(* Logix 5000 project; controller Electronic_Displays vendor 1 type 14 code 65 rev 17.4; software revision 17.01; part 3 of 9 *)
(* tags used below, declared in another part *)
   EDV : LEDSIGN;
   ENABLE : DINT;

ADD_ON_INSTRUCTION NumberSignRTA   (* revision 1.0, ExecuteEnableInFalse *)
// Number Sign
// Send only Numbers
// Revision note:
// Original Release
// 03-30-2013
// c.elston
VAR_IN_OUT
   Address : STRING; {required}   // "01" = address 01 "02" = address 02 etc...(see protocol)
   NumberValue : DINT; {required}   // Actual number value (DINT Format)
END_VAR
VAR_OUTPUT
   EN : BOOL; {visible}   // Instruction Interface Enable Bit
   DN : BOOL; {visible}   // Instruction Interface Done Bit
   ER : BOOL; {visible}   // Instruction Interface Error Bit
   IP : BOOL; {visible}   // Instruction Interface InProcess Bit
END_VAR
VAR_IN_OUT
   map_SignInput : SINT[100]; {required}   // Ethernet/IP LEDSIGN.I Data I/O Mapping
   map_SignOutput : SINT[100]; {required}   // Ethernet/IP LEDSIGN.O Data I/O Mapping
   PacketSent : STRING; {required}   // The actual packet sent to the sign.
END_VAR
VAR
   SEQ : DINT;   // Sequence Number
   OktoCycle : BOOL;   // Ok to Cycle
   InCycle : BOOL;   // Incycle
   Error : BOOL;   // Error
   Enabled : BOOL;   // Enable ON Bit
   Done : BOOL;   // Done
   Disabled : BOOL;   // Disabled OFF Bit
   SignETX : STRING := '$03';   // DO NOT EDIT = $03 the number sign protocol is different than EDV signs
   SignAddress : STRING;
   SignSTX : STRING := '$02';   // DO NOT EDIT = $02 the number sign protocol is different than EDV signs
   SignNULL : STRING;
   TotalPacketCount : DINT[7];   // Total Character Count
   Select : DINT;   // Packet Array Select
   PacketMax : DINT := 82;   // Max Packet Count
   PacketCount : DINT[7];
   Packet6Offset : DINT;
   Packet5Offset : DINT;
   Packet4Offset : DINT;
   Packet3Offset : DINT;
   Packet2Offset : DINT;
   Packet1Offset : DINT;
   Packet : STRING[7];   // Packet Array to send to sign
   SignNumberValue : DINT;
   SignVariable1Value : STRING;
   SignNumberValue1 : STRING;
   SignNumberValueSTRING : STRING;
END_VAR

ROUTINE EnableInFalse   (* ladder *)
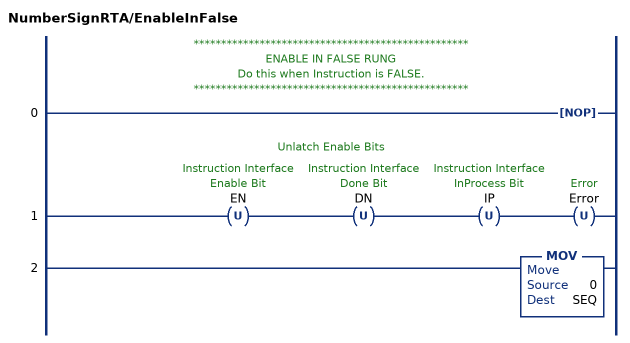
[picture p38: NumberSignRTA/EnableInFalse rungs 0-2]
   // **************************************************
   // ENABLE IN FALSE RUNG
   // Do this when Instruction is FALSE.
   // **************************************************
   0: NOP();
   // Unlatch Enable Bits
   1: OTU(EN)OTU(DN)OTU(IP)OTU(Error);
   2: MOV(0,SEQ);
END_ROUTINE

ROUTINE Logic   (* ladder *)
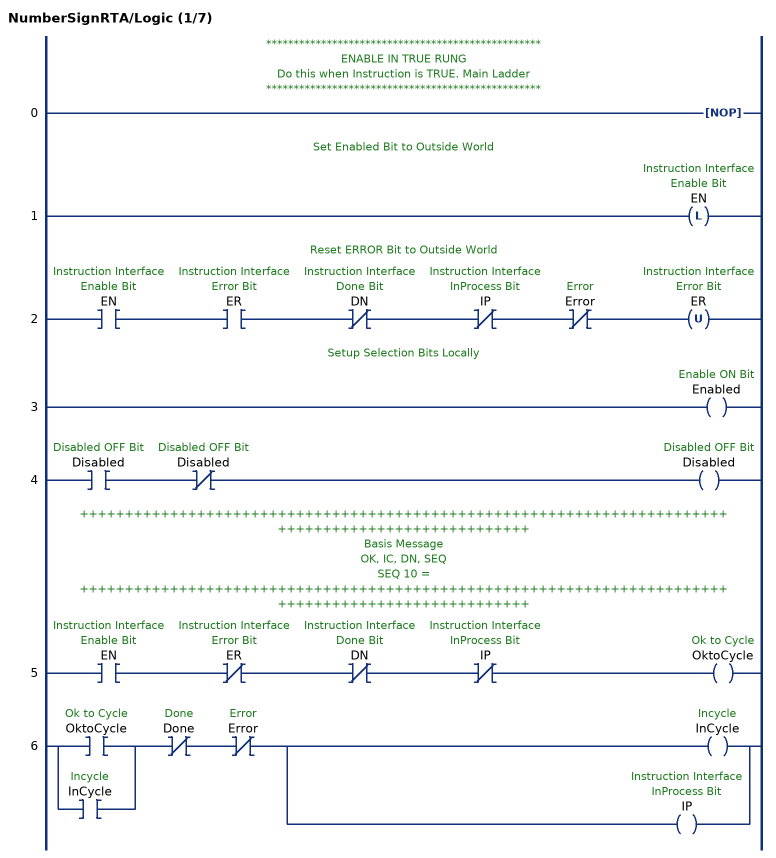
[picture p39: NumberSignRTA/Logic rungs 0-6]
   // **************************************************
   // ENABLE IN TRUE RUNG
   // Do this when Instruction is TRUE. Main Ladder
   // **************************************************
   0: NOP();
   // Set Enabled Bit to Outside World
   1: OTL(EN);
   // Reset ERROR Bit to Outside World
   2: XIC(EN)XIC(ER)XIO(DN)XIO(IP)XIO(Error)OTU(ER);
   // Setup Selection Bits Locally
   3: OTE(Enabled);
   4: XIC(Disabled)XIO(Disabled)OTE(Disabled);
   // ++++++++++++++++++++++++++++++++++++++++++++++++++++++++++++++++++++++++++++++++++++++++++++++++++++
   // Basis Message
   // OK, IC, DN, SEQ
   // SEQ 10 =
   // ++++++++++++++++++++++++++++++++++++++++++++++++++++++++++++++++++++++++++++++++++++++++++++++++++++
   5: XIC(EN)XIO(ER)XIO(DN)XIO(IP)OTE(OktoCycle);
   6: [XIC(OktoCycle) ,XIC(InCycle) ]XIO(Done)XIO(Error)[OTE(InCycle) ,OTE(IP) ];
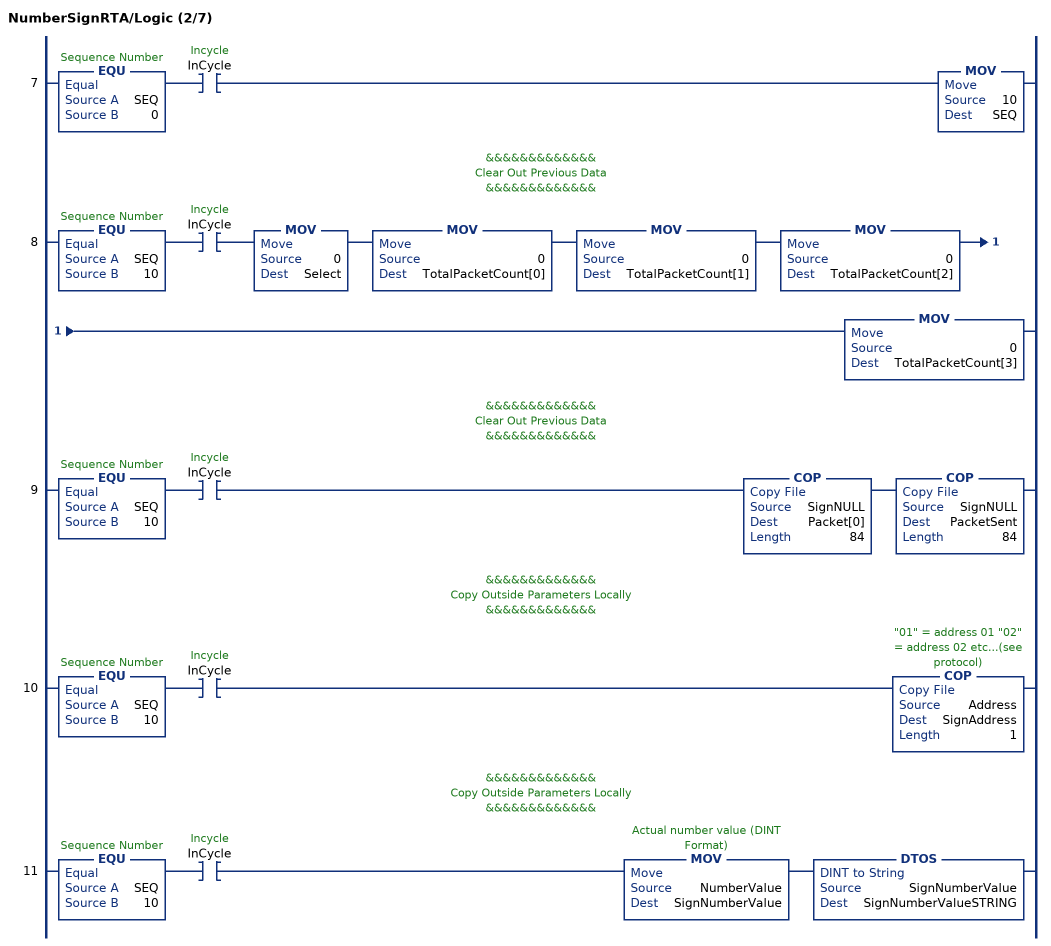
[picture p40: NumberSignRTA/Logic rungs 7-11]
   7: EQU(SEQ,0)XIC(InCycle)MOV(10,SEQ);
   // &&&&&&&&&&&&&
   // Clear Out Previous Data
   // &&&&&&&&&&&&&
   8: EQU(SEQ,10)XIC(InCycle)MOV(0,Select)MOV(0,TotalPacketCount[0])MOV(0,TotalPacketCount[1])MOV(0,TotalPacketCount[2])MOV(0,TotalPacketCount[3]);
   // &&&&&&&&&&&&&
   // Clear Out Previous Data
   // &&&&&&&&&&&&&
   9: EQU(SEQ,10)XIC(InCycle)COP(SignNULL,Packet[0],84)COP(SignNULL,PacketSent,84);
   // &&&&&&&&&&&&&
   // Copy Outside Parameters Locally
   // &&&&&&&&&&&&&
   10: EQU(SEQ,10)XIC(InCycle)COP(Address,SignAddress,1);
   // &&&&&&&&&&&&&
   // Copy Outside Parameters Locally
   // &&&&&&&&&&&&&
   11: EQU(SEQ,10)XIC(InCycle)MOV(NumberValue,SignNumberValue)DTOS(SignNumberValue,SignNumberValueSTRING);
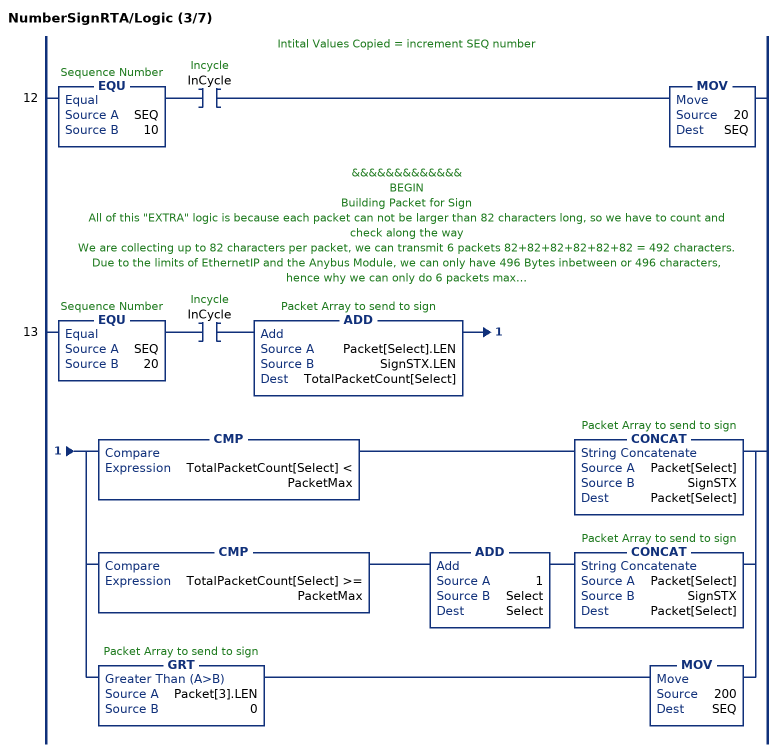
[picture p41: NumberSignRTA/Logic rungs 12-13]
   // Intital Values Copied = increment SEQ number
   12: EQU(SEQ,10)XIC(InCycle)MOV(20,SEQ);
   // &&&&&&&&&&&&&
   // BEGIN
   // Building Packet for Sign
   // All of this "EXTRA" logic is because each packet can not be larger than 82 characters long, so we have to count and check along the way
   // We are collecting up to 82 characters per packet, we can transmit 6 packets 82+82+82+82+82+82 = 492 characters.
   // Due to the limits of EthernetIP and the Anybus Module, we can only have 496 Bytes inbetween or 496 characters, hence why we can only do 6 packets max.
   // Once we exceed this, we will fault and ERROR trap any windy typing people.
   // In this instruction below, it's so small, we are only using 3 packets max.
   // &&&&&&&&&&&&&
   13: EQU(SEQ,20)XIC(InCycle)ADD(Packet[Select].LEN,SignSTX.LEN,TotalPacketCount[Select])[CMP(TotalPacketCount[Select] < PacketMax) CONCAT(Packet[Select],SignSTX,Packet[Select]) ,CMP(TotalPacketCount[Select] >= PacketMax) ADD(1,Select,Select) CONCAT(Packet[Select],SignSTX,Packet[Select]) ,GRT(Packet[3].LEN,0) MOV(200,SEQ) ];
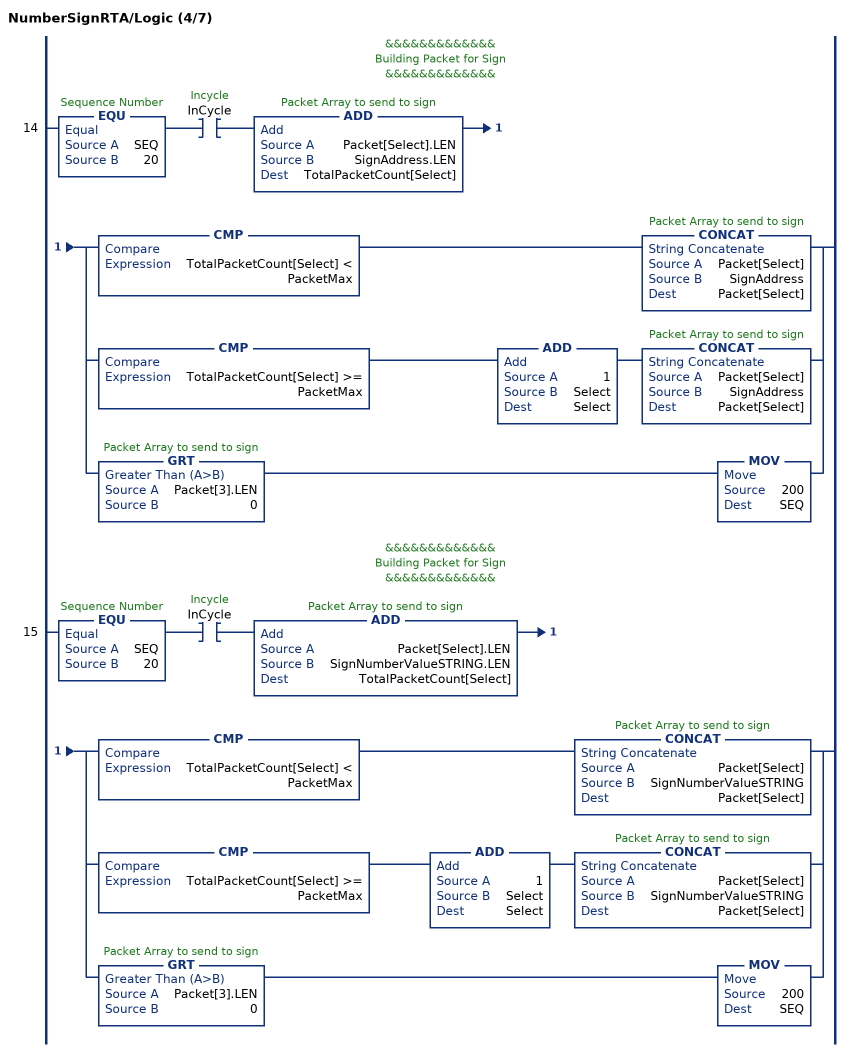
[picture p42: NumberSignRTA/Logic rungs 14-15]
   // &&&&&&&&&&&&&
   // Building Packet for Sign
   // &&&&&&&&&&&&&
   14: EQU(SEQ,20)XIC(InCycle)ADD(Packet[Select].LEN,SignAddress.LEN,TotalPacketCount[Select])[CMP(TotalPacketCount[Select] < PacketMax) CONCAT(Packet[Select],SignAddress,Packet[Select]) ,CMP(TotalPacketCount[Select] >= PacketMax) ADD(1,Select,Select) CONCAT(Packet[Select],SignAddress,Packet[Select]) ,GRT(Packet[3].LEN,0) MOV(200,SEQ) ];
   // &&&&&&&&&&&&&
   // Building Packet for Sign
   // &&&&&&&&&&&&&
   15: EQU(SEQ,20)XIC(InCycle)ADD(Packet[Select].LEN,SignNumberValueSTRING.LEN,TotalPacketCount[Select])[CMP(TotalPacketCount[Select] < PacketMax) CONCAT(Packet[Select],SignNumberValueSTRING,Packet[Select]) ,CMP(TotalPacketCount[Select] >= PacketMax) ADD(1,Select,Select) CONCAT(Packet[Select],SignNumberValueSTRING,Packet[Select]) ,GRT(Packet[3].LEN,0) MOV(200,SEQ) ];
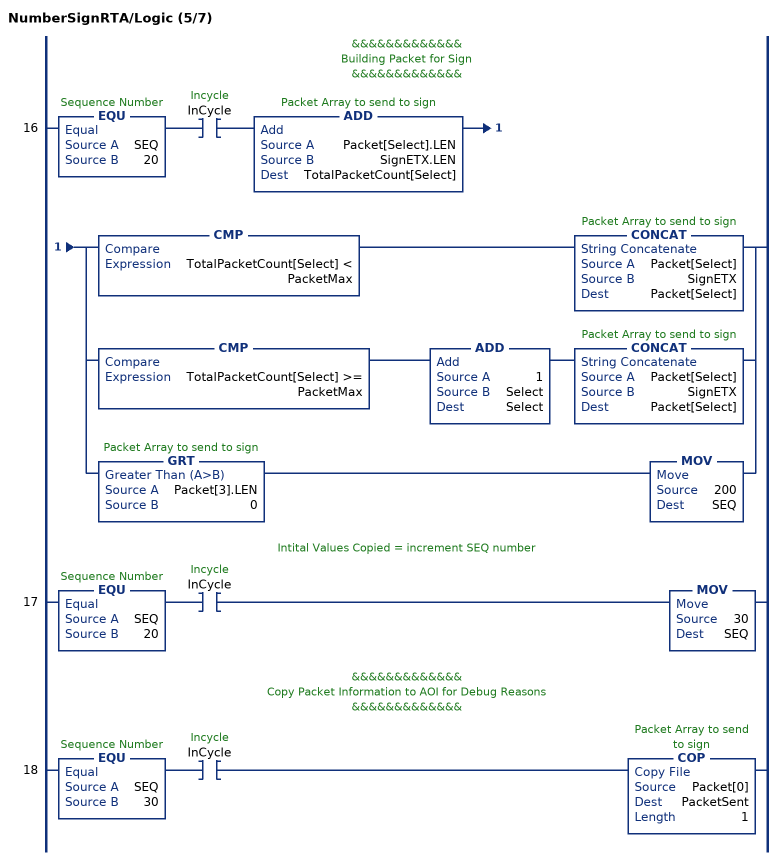
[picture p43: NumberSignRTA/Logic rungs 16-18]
   // &&&&&&&&&&&&&
   // Building Packet for Sign
   // &&&&&&&&&&&&&
   16: EQU(SEQ,20)XIC(InCycle)ADD(Packet[Select].LEN,SignETX.LEN,TotalPacketCount[Select])[CMP(TotalPacketCount[Select] < PacketMax) CONCAT(Packet[Select],SignETX,Packet[Select]) ,CMP(TotalPacketCount[Select] >= PacketMax) ADD(1,Select,Select) CONCAT(Packet[Select],SignETX,Packet[Select]) ,GRT(Packet[3].LEN,0) MOV(200,SEQ) ];
   // Intital Values Copied = increment SEQ number
   17: EQU(SEQ,20)XIC(InCycle)MOV(30,SEQ);
   // &&&&&&&&&&&&&
   // Copy Packet Information to AOI for Debug Reasons
   // &&&&&&&&&&&&&
   18: EQU(SEQ,30)XIC(InCycle)COP(Packet[0],PacketSent,1);
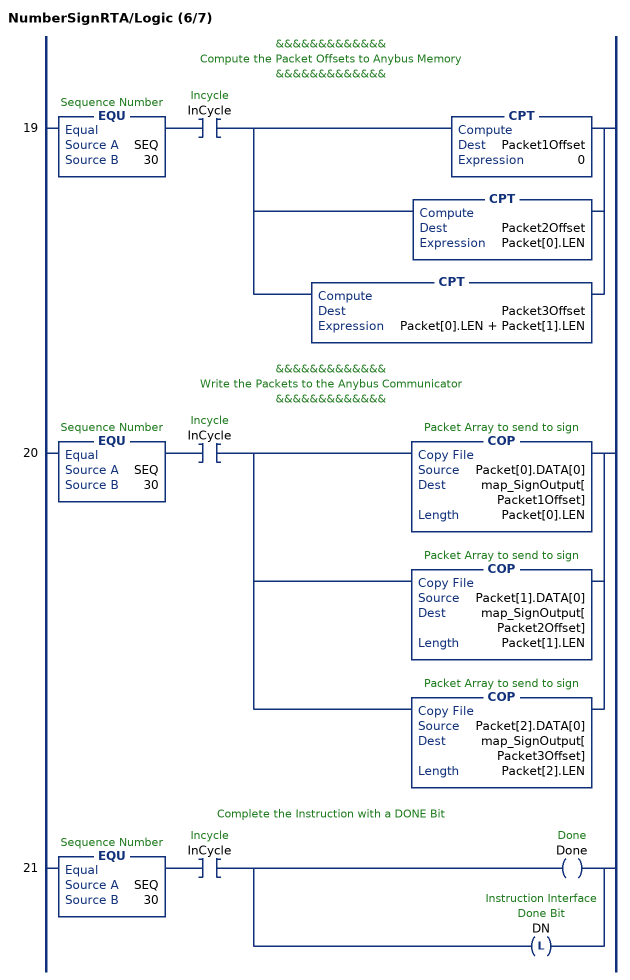
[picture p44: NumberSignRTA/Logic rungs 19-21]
   // &&&&&&&&&&&&&
   // Compute the Packet Offsets to Anybus Memory
   // &&&&&&&&&&&&&
   19: EQU(SEQ,30)XIC(InCycle)[CPT(Packet1Offset,0) ,CPT(Packet2Offset,Packet[0].LEN) ,CPT(Packet3Offset,Packet[0].LEN + Packet[1].LEN) ];
   // &&&&&&&&&&&&&
   // Write the Packets to the Anybus Communicator
   // &&&&&&&&&&&&&
   20: EQU(SEQ,30)XIC(InCycle)[COP(Packet[0].DATA[0],map_SignOutput[Packet1Offset],Packet[0].LEN) ,COP(Packet[1].DATA[0],map_SignOutput[Packet2Offset],Packet[1].LEN) ,COP(Packet[2].DATA[0],map_SignOutput[Packet3Offset],Packet[2].LEN) ];
   // Complete the Instruction with a DONE Bit
   21: EQU(SEQ,30)XIC(InCycle)[OTE(Done) ,OTL(DN) ];
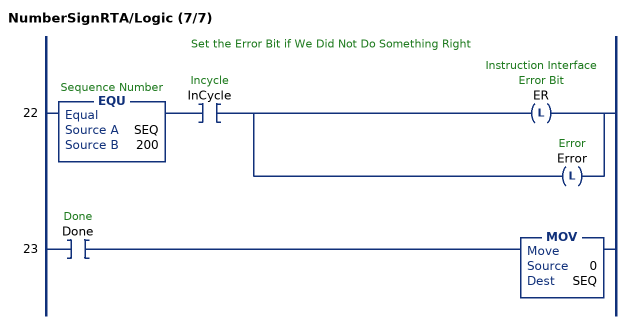
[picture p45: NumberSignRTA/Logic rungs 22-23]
   // Set the Error Bit if We Did Not Do Something Right
   22: EQU(SEQ,200)XIC(InCycle)[OTL(ER) ,OTL(Error) ];
   23: XIC(Done)MOV(0,SEQ);
END_ROUTINE
END_ADD_ON_INSTRUCTION

ADD_ON_INSTRUCTION ResetSign   (* revision 1.0, ExecuteEnableInFalse *)
// Reset Sign
// Erases All
// Variable Memory
// Revision note:
// Original Release
// 11-01-2012
// c.elston
VAR_IN_OUT
   Address : STRING; {required}   // "00" = all signs "01" = address 01 "02" = address 02 etc...(see protocol)
END_VAR
VAR_OUTPUT
   EN : BOOL; {visible}   // Instruction Interface Enable Bit
   DN : BOOL; {visible}   // Instruction Interface Done Bit
   ER : BOOL; {visible}   // Instruction Interface Error Bit
   IP : BOOL; {visible}   // Instruction Interface InProcess Bit
END_VAR
VAR_IN_OUT
   map_SignInput : SINT[32]; {required}   // Ethernet/IP LEDSIGN.I Data I/O Mapping
   map_SignOutput : SINT[496]; {required}   // Ethernet/IP LEDSIGN.O Data I/O Mapping
   Packet1Sent : STRING; {required}   // The actual packet sent to the sign (Packet1)
   Packet2Sent : STRING; {required}   // The actual packet sent to the sign (Packet2)
   Packet3Sent : STRING; {required}   // The actual packet sent to the sign (Packet3)
END_VAR
VAR
   SEQ : DINT;   // Sequence Number
   OktoCycle : BOOL;   // Ok to Cycle
   InCycle : BOOL;   // Incycle
   Error : BOOL;   // Error
   Enabled : BOOL;   // Enable ON Bit
   Done : BOOL;   // Done
   Disabled : BOOL;   // Disabled OFF Bit
   SignETX : STRING := '^C';   // DO NOT EDIT = ^C
   SignFileLabel : STRING;
   SignSOH : STRING := '^A';   // DO NOT EDIT = ^A
   SignAddress : STRING;
   SignSTX : STRING := '^B';   // DO NOT EDIT = ^B
   SignNULL : STRING;
   SignResetMemoryCommand : STRING := 'CM';   // DO NOT EDIT = SM
   SignCommandCode : STRING := 'C';   // DO NOT EDIT = C
   TotalPacketCount : DINT[7];   // Total Character Count
   Select : DINT;   // Packet Array Select
   PacketMax : DINT := 82;   // Max Packet Count
   PacketCount : DINT[7];
   Packet6Offset : DINT;
   Packet5Offset : DINT;
   Packet4Offset : DINT;
   Packet3Offset : DINT;
   Packet2Offset : DINT;
   Packet1Offset : DINT;
   Packet : STRING[7];   // Packet Array to send to sign
END_VAR

ROUTINE EnableInFalse   (* ladder *)
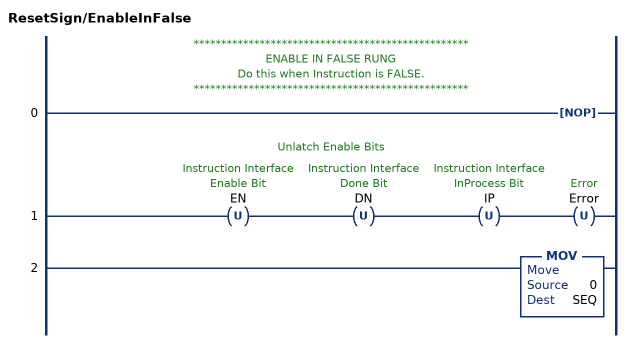
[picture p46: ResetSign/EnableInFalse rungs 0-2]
   // **************************************************
   // ENABLE IN FALSE RUNG
   // Do this when Instruction is FALSE.
   // **************************************************
   0: NOP();
   // Unlatch Enable Bits
   1: OTU(EN)OTU(DN)OTU(IP)OTU(Error);
   2: MOV(0,SEQ);
END_ROUTINE

ROUTINE Logic   (* ladder *)
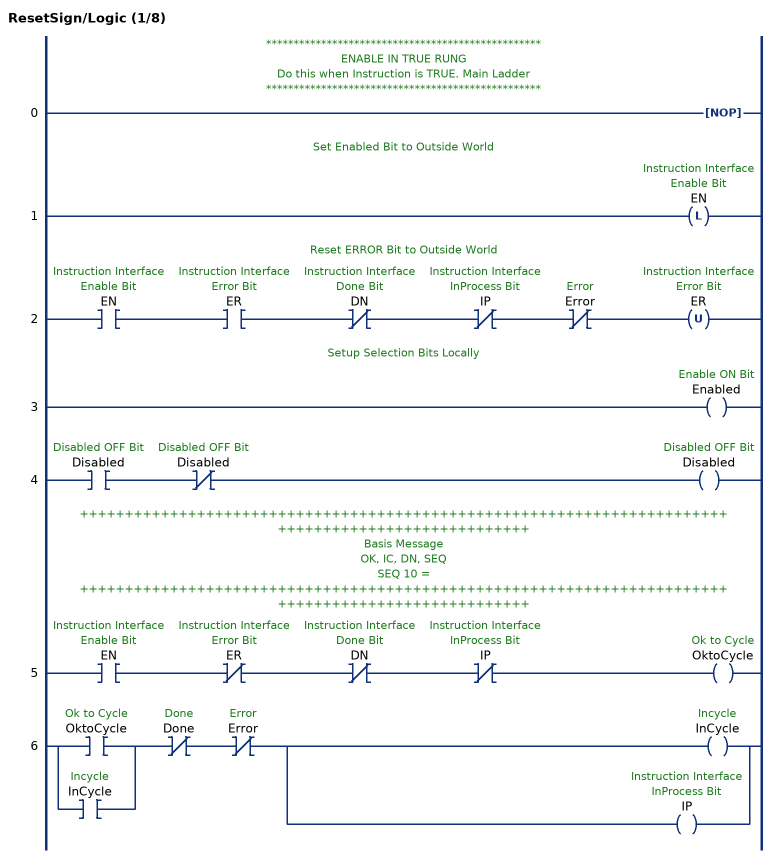
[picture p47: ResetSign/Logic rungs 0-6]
   // **************************************************
   // ENABLE IN TRUE RUNG
   // Do this when Instruction is TRUE. Main Ladder
   // **************************************************
   0: NOP();
   // Set Enabled Bit to Outside World
   1: OTL(EN);
   // Reset ERROR Bit to Outside World
   2: XIC(EN)XIC(ER)XIO(DN)XIO(IP)XIO(Error)OTU(ER);
   // Setup Selection Bits Locally
   3: OTE(Enabled);
   4: XIC(Disabled)XIO(Disabled)OTE(Disabled);
   // ++++++++++++++++++++++++++++++++++++++++++++++++++++++++++++++++++++++++++++++++++++++++++++++++++++
   // Basis Message
   // OK, IC, DN, SEQ
   // SEQ 10 =
   // ++++++++++++++++++++++++++++++++++++++++++++++++++++++++++++++++++++++++++++++++++++++++++++++++++++
   5: XIC(EN)XIO(ER)XIO(DN)XIO(IP)OTE(OktoCycle);
   6: [XIC(OktoCycle) ,XIC(InCycle) ]XIO(Done)XIO(Error)[OTE(InCycle) ,OTE(IP) ];
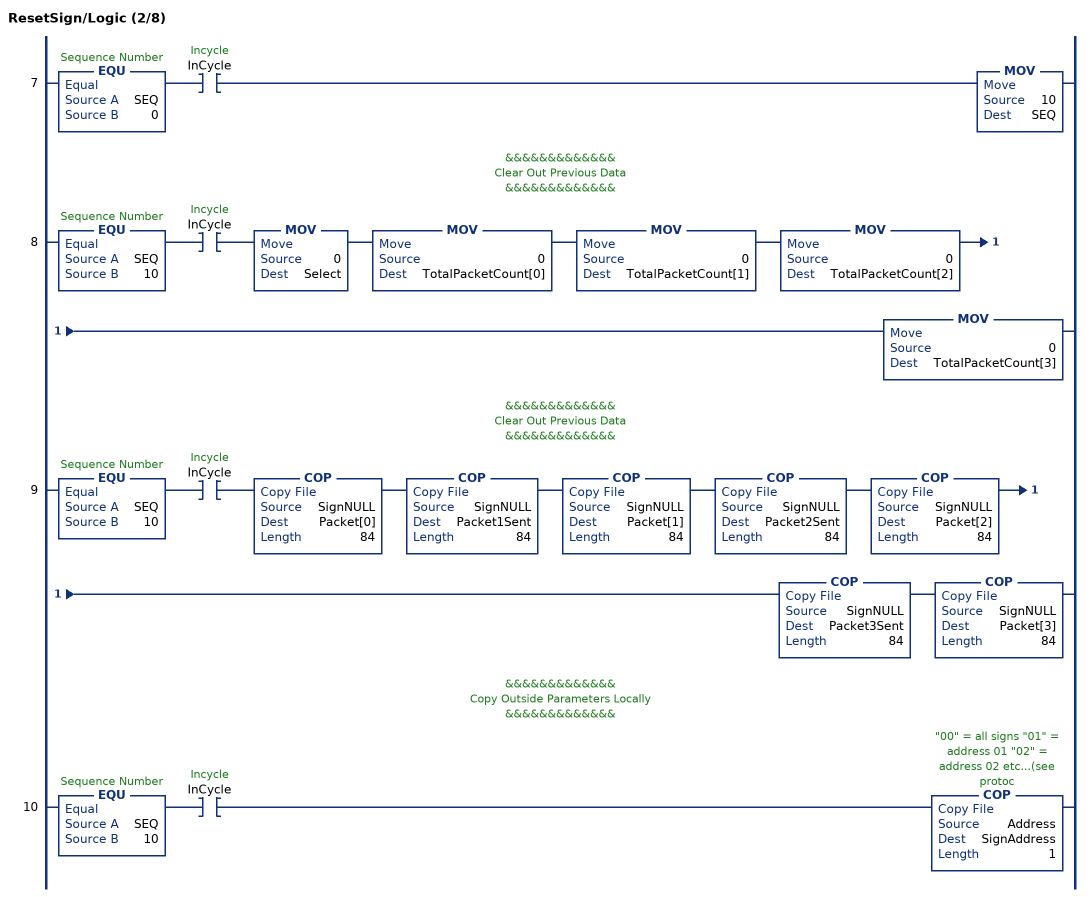
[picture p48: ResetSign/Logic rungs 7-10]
   7: EQU(SEQ,0)XIC(InCycle)MOV(10,SEQ);
   // &&&&&&&&&&&&&
   // Clear Out Previous Data
   // &&&&&&&&&&&&&
   8: EQU(SEQ,10)XIC(InCycle)MOV(0,Select)MOV(0,TotalPacketCount[0])MOV(0,TotalPacketCount[1])MOV(0,TotalPacketCount[2])MOV(0,TotalPacketCount[3]);
   // &&&&&&&&&&&&&
   // Clear Out Previous Data
   // &&&&&&&&&&&&&
   9: EQU(SEQ,10)XIC(InCycle)COP(SignNULL,Packet[0],84)COP(SignNULL,Packet1Sent,84)COP(SignNULL,Packet[1],84)COP(SignNULL,Packet2Sent,84)COP(SignNULL,Packet[2],84)COP(SignNULL,Packet3Sent,84)COP(SignNULL,Packet[3],84);
   // &&&&&&&&&&&&&
   // Copy Outside Parameters Locally
   // &&&&&&&&&&&&&
   10: EQU(SEQ,10)XIC(InCycle)COP(Address,SignAddress,1);
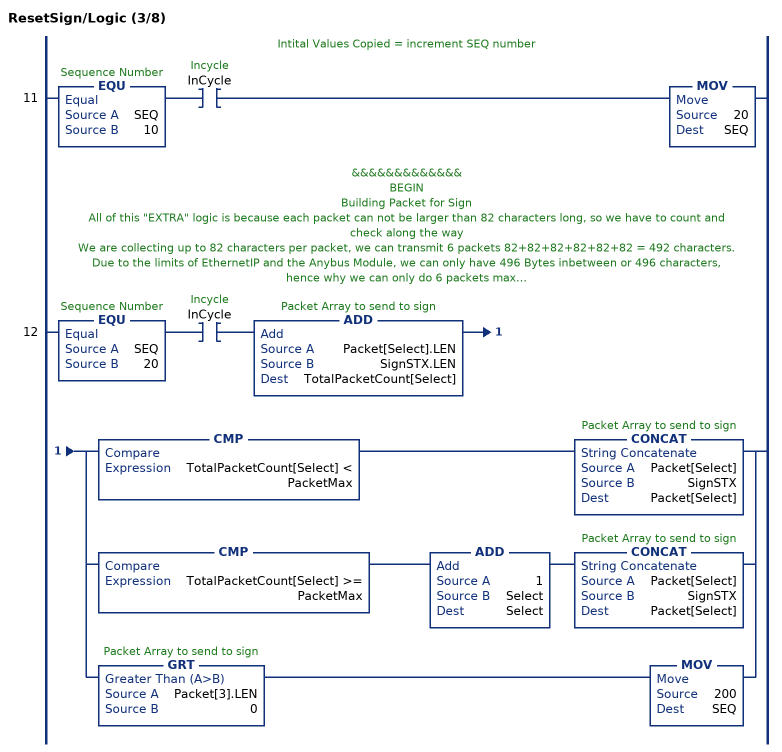
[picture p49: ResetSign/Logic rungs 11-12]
   // Intital Values Copied = increment SEQ number
   11: EQU(SEQ,10)XIC(InCycle)MOV(20,SEQ);
   // &&&&&&&&&&&&&
   // BEGIN
   // Building Packet for Sign
   // All of this "EXTRA" logic is because each packet can not be larger than 82 characters long, so we have to count and check along the way
   // We are collecting up to 82 characters per packet, we can transmit 6 packets 82+82+82+82+82+82 = 492 characters.
   // Due to the limits of EthernetIP and the Anybus Module, we can only have 496 Bytes inbetween or 496 characters, hence why we can only do 6 packets max.
   // Once we exceed this, we will fault and ERROR trap any windy typing people.
   // In this instruction below, it's so small, we are only using 3 packets max.
   // &&&&&&&&&&&&&
   12: EQU(SEQ,20)XIC(InCycle)ADD(Packet[Select].LEN,SignSTX.LEN,TotalPacketCount[Select])[CMP(TotalPacketCount[Select] < PacketMax) CONCAT(Packet[Select],SignSTX,Packet[Select]) ,CMP(TotalPacketCount[Select] >= PacketMax) ADD(1,Select,Select) CONCAT(Packet[Select],SignSTX,Packet[Select]) ,GRT(Packet[3].LEN,0) MOV(200,SEQ) ];
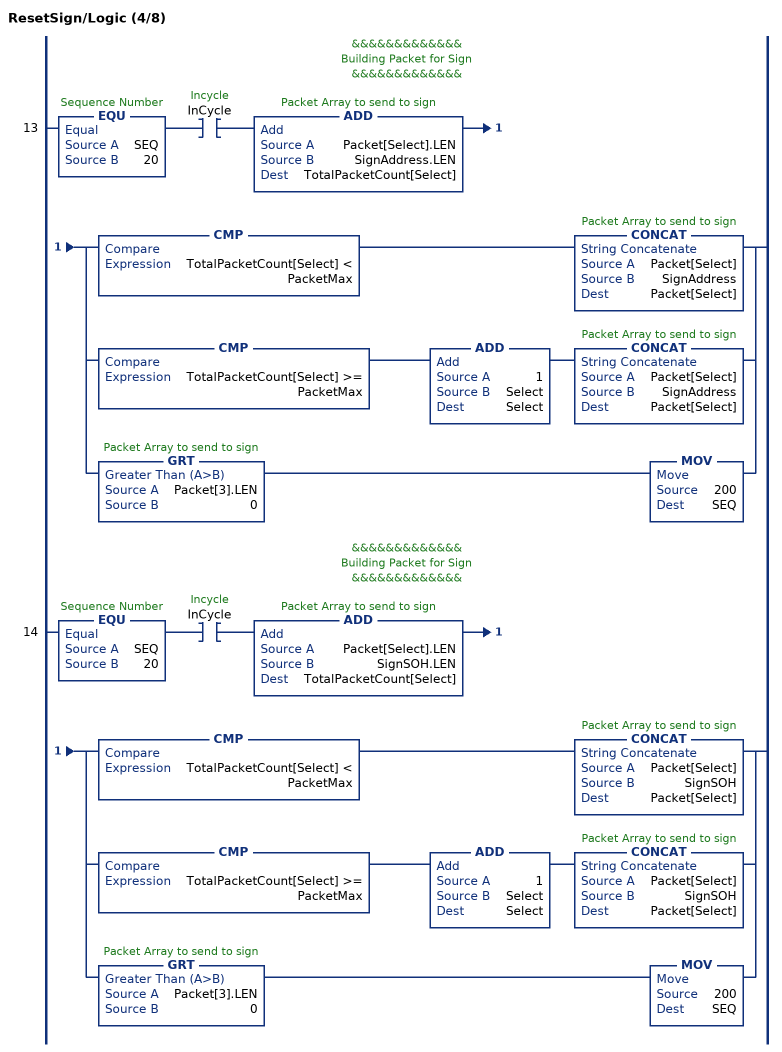
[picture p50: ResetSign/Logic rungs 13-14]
   // &&&&&&&&&&&&&
   // Building Packet for Sign
   // &&&&&&&&&&&&&
   13: EQU(SEQ,20)XIC(InCycle)ADD(Packet[Select].LEN,SignAddress.LEN,TotalPacketCount[Select])[CMP(TotalPacketCount[Select] < PacketMax) CONCAT(Packet[Select],SignAddress,Packet[Select]) ,CMP(TotalPacketCount[Select] >= PacketMax) ADD(1,Select,Select) CONCAT(Packet[Select],SignAddress,Packet[Select]) ,GRT(Packet[3].LEN,0) MOV(200,SEQ) ];
   // &&&&&&&&&&&&&
   // Building Packet for Sign
   // &&&&&&&&&&&&&
   14: EQU(SEQ,20)XIC(InCycle)ADD(Packet[Select].LEN,SignSOH.LEN,TotalPacketCount[Select])[CMP(TotalPacketCount[Select] < PacketMax) CONCAT(Packet[Select],SignSOH,Packet[Select]) ,CMP(TotalPacketCount[Select] >= PacketMax) ADD(1,Select,Select) CONCAT(Packet[Select],SignSOH,Packet[Select]) ,GRT(Packet[3].LEN,0) MOV(200,SEQ) ];
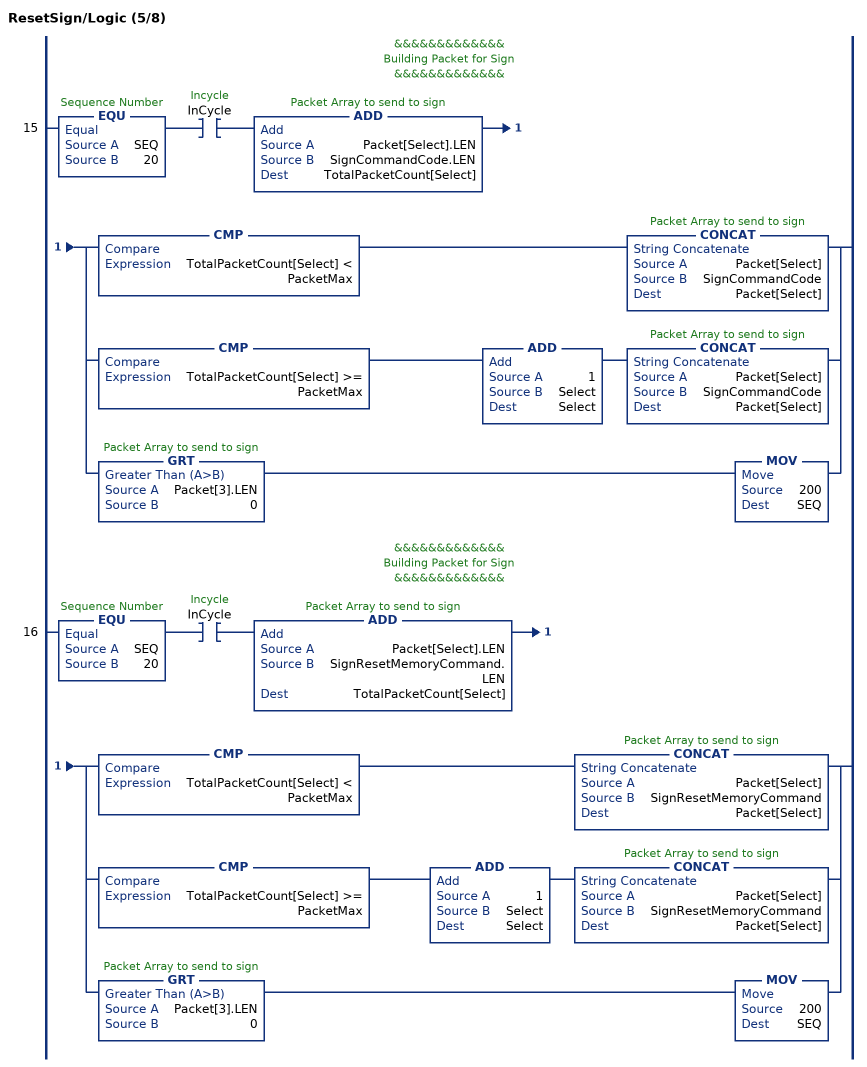
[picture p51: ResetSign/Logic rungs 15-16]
   // &&&&&&&&&&&&&
   // Building Packet for Sign
   // &&&&&&&&&&&&&
   15: EQU(SEQ,20)XIC(InCycle)ADD(Packet[Select].LEN,SignCommandCode.LEN,TotalPacketCount[Select])[CMP(TotalPacketCount[Select] < PacketMax) CONCAT(Packet[Select],SignCommandCode,Packet[Select]) ,CMP(TotalPacketCount[Select] >= PacketMax) ADD(1,Select,Select) CONCAT(Packet[Select],SignCommandCode,Packet[Select]) ,GRT(Packet[3].LEN,0) MOV(200,SEQ) ];
   // &&&&&&&&&&&&&
   // Building Packet for Sign
   // &&&&&&&&&&&&&
   16: EQU(SEQ,20)XIC(InCycle)ADD(Packet[Select].LEN,SignResetMemoryCommand.LEN,TotalPacketCount[Select])[CMP(TotalPacketCount[Select] < PacketMax) CONCAT(Packet[Select],SignResetMemoryCommand,Packet[Select]) ,CMP(TotalPacketCount[Select] >= PacketMax) ADD(1,Select,Select) CONCAT(Packet[Select],SignResetMemoryCommand,Packet[Select]) ,GRT(Packet[3].LEN,0) MOV(200,SEQ) ];
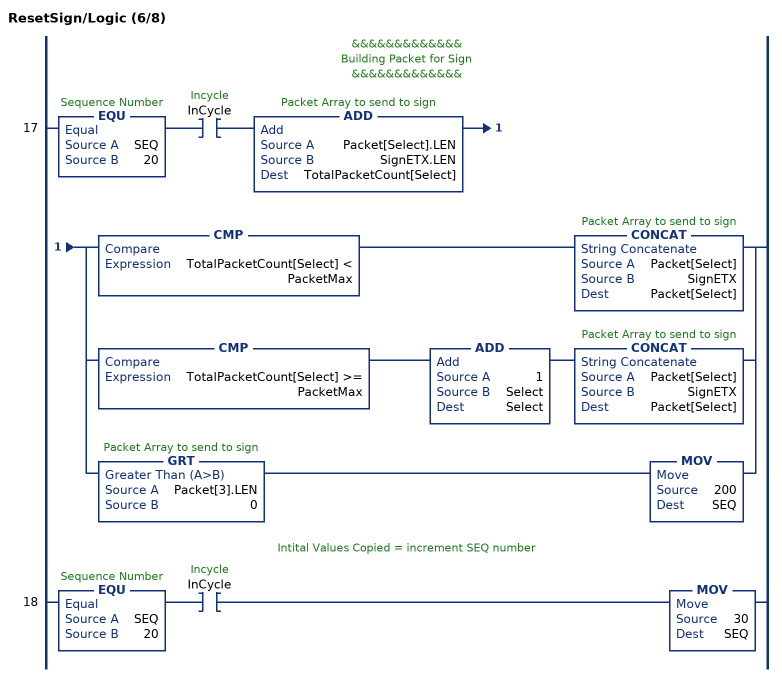
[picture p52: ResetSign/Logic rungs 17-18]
   // &&&&&&&&&&&&&
   // Building Packet for Sign
   // &&&&&&&&&&&&&
   17: EQU(SEQ,20)XIC(InCycle)ADD(Packet[Select].LEN,SignETX.LEN,TotalPacketCount[Select])[CMP(TotalPacketCount[Select] < PacketMax) CONCAT(Packet[Select],SignETX,Packet[Select]) ,CMP(TotalPacketCount[Select] >= PacketMax) ADD(1,Select,Select) CONCAT(Packet[Select],SignETX,Packet[Select]) ,GRT(Packet[3].LEN,0) MOV(200,SEQ) ];
   // Intital Values Copied = increment SEQ number
   18: EQU(SEQ,20)XIC(InCycle)MOV(30,SEQ);
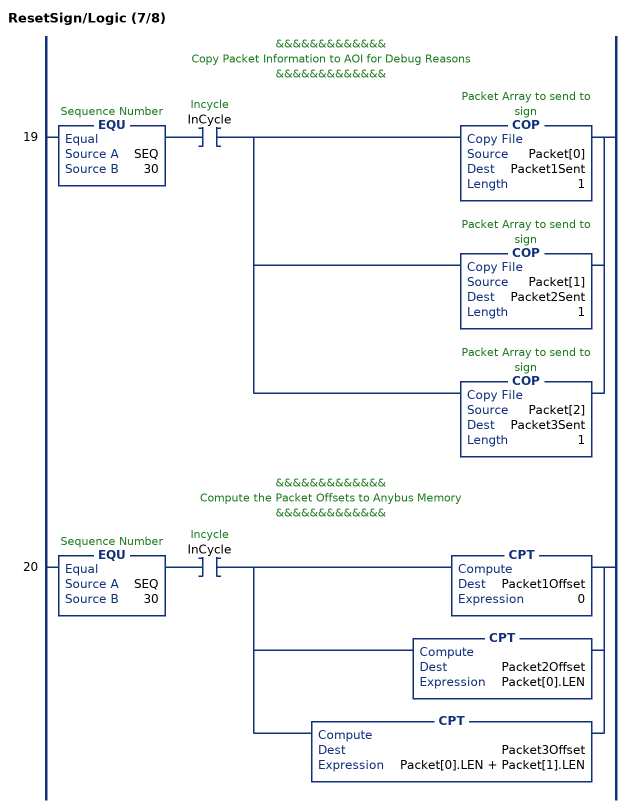
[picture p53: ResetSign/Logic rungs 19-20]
   // &&&&&&&&&&&&&
   // Copy Packet Information to AOI for Debug Reasons
   // &&&&&&&&&&&&&
   19: EQU(SEQ,30)XIC(InCycle)[COP(Packet[0],Packet1Sent,1) ,COP(Packet[1],Packet2Sent,1) ,COP(Packet[2],Packet3Sent,1) ];
   // &&&&&&&&&&&&&
   // Compute the Packet Offsets to Anybus Memory
   // &&&&&&&&&&&&&
   20: EQU(SEQ,30)XIC(InCycle)[CPT(Packet1Offset,0) ,CPT(Packet2Offset,Packet[0].LEN) ,CPT(Packet3Offset,Packet[0].LEN + Packet[1].LEN) ];
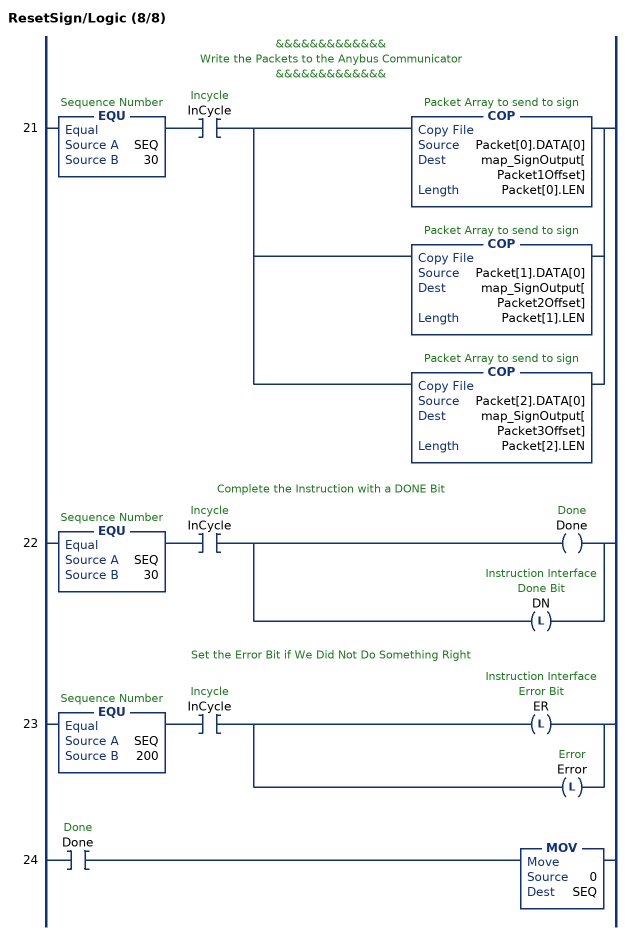
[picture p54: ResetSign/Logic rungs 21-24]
   // &&&&&&&&&&&&&
   // Write the Packets to the Anybus Communicator
   // &&&&&&&&&&&&&
   21: EQU(SEQ,30)XIC(InCycle)[COP(Packet[0].DATA[0],map_SignOutput[Packet1Offset],Packet[0].LEN) ,COP(Packet[1].DATA[0],map_SignOutput[Packet2Offset],Packet[1].LEN) ,COP(Packet[2].DATA[0],map_SignOutput[Packet3Offset],Packet[2].LEN) ];
   // Complete the Instruction with a DONE Bit
   22: EQU(SEQ,30)XIC(InCycle)[OTE(Done) ,OTL(DN) ];
   // Set the Error Bit if We Did Not Do Something Right
   23: EQU(SEQ,200)XIC(InCycle)[OTL(ER) ,OTL(Error) ];
   24: XIC(Done)MOV(0,SEQ);
END_ROUTINE
END_ADD_ON_INSTRUCTION

ADD_ON_INSTRUCTION SendSignMessage   (* revision 1.0, ExecuteEnableInFalse *)
// Send up to
// Four Lines
// to LED Sign
// Revision note:
// Original Release
// 11-01-2012
// c.elston
VAR_IN_OUT
   Address : STRING; {required}   // "00" = all signs "01" = address 01 "02" = address 02 etc...(see protocol)
   CommandCode : STRING; {required}   // "A" = text "B" = variable "C" = special "D" = text,norestart etc...(see protocol)
   FileLabel : STRING; {required}   // "A" = default etc...(see protocol)
END_VAR
VAR_INPUT
   ENText1Message : BOOL; {visible}   // 0 = don't sent message 1 = send message
END_VAR
VAR_IN_OUT
   Text1Message : STRING; {required}   // Actual Text Message to be Written to Screen (Line 1) 4 x 1 configuration
END_VAR
VAR_INPUT
   ENText2Message : BOOL; {visible}   // 0 = don't sent message 1 = send message
END_VAR
VAR_IN_OUT
   Text2Message : STRING; {required}   // Actual Text Message to be Written to Screen (Line 2) 4 x 1 configuration
END_VAR
VAR_INPUT
   ENText3Message : BOOL; {visible}   // 0 = don't sent message 1 = send message
END_VAR
VAR_IN_OUT
   Text3Message : STRING; {required}   // Actual Text Message to be Written to Screen (Line 3) 4 x 1 configuration
END_VAR
VAR_INPUT
   ENText4Message : BOOL; {visible}   // 0 = don't sent message 1 = send message
END_VAR
VAR_IN_OUT
   Text4Message : STRING; {required}   // Actual Text Message to be Written to Screen (Line 4) 4 x 1 configuration
END_VAR
VAR_INPUT
   ENTextFormats : BOOL; {visible}   // 0 = no additional text formatting 1 = enable text formatting
END_VAR
VAR_IN_OUT
   TextFont : STRING; {required}   // "0" = default "1" = SF7 "2" = SF10 "3" = SS16 "4" = SF16
   TextColor : STRING; {required}   // "0" = Red (default) "1" = Green "2" = Yellow "3" = Rainbow1
   TextAlign : STRING; {required}   // "M"=middle line "T"=top line "B"=bottom line "F"=fill (best for variables) "L"=left "R"=right
   TextAttribute : STRING; {required}   // "0"=flashing off "1"=flashing on "2"=wide off "3"=wide on "4"=bold off "5"=bold on
END_VAR
VAR_INPUT
   ENTextSpecials : BOOL; {visible}   // 0 = no additional text special formatting 1 = enable text special formatting
END_VAR
VAR_IN_OUT
   TextEffect : STRING; {required}   // "S"=scrolls "H"=hold "F"=flash "A"=slide up "B"=slide down "C"=slide left "D"=slide right "a"=roll up "b"=roll down "c"=roll left "d"=roll right
   TextSpeed : STRING; {required}   // 1 - 8 "3" = Default (see protocol)
   TextPause : STRING; {required}   // 00 - 99 "02" = Default (see protocol) [must be two digits] if not will not work!
END_VAR
VAR_INPUT
   ENVariable1Message : BOOL; {visible}   // 0 = don't sent embedded variable 1 = send embedded variable
END_VAR
VAR_IN_OUT
   Variable1Name : STRING; {required}   // Name of variable Default is = U
END_VAR
VAR_INPUT
   ENVariable2Message : BOOL; {visible}   // 0 = don't sent embedded variable 1 = send embedded variable
END_VAR
VAR_IN_OUT
   Variable2Name : STRING; {required}   // Name of variable Default is = V
END_VAR
VAR_INPUT
   ENVariable3Message : BOOL; {visible}   // 0 = don't sent embedded variable 1 = send embedded variable
END_VAR
VAR_IN_OUT
   Variable3Name : STRING; {required}   // Name of variable Default is = W
END_VAR
VAR_INPUT
   ENVariable4Message : BOOL; {visible}   // 0 = don't sent embedded variable 1 = send embedded variable
END_VAR
VAR_IN_OUT
   Variable4Name : STRING; {required}   // Name of variable Default is = X
END_VAR
VAR_INPUT
   ENVariableFormats : BOOL; {visible}   // 0 = no additional text formatting 1 = enable text formatting
END_VAR
VAR_IN_OUT
   VariableFont : STRING; {required}   // "0" = default "1" = SF7 "2" = SF10 "3" = SS16 "4" = SF16 etc...(see protocol)
   VariableColor : STRING; {required}   // "0" = Red (default) "1" = Green "2" = Yellow "3" = Rainbow1
   VariableAttribute : STRING; {required}   // "0"=flashing off "1"=flashing on "2"=wide off "3"=wide on "4"=bold off "5"=bold on
END_VAR
VAR_OUTPUT
   EN : BOOL; {visible}   // Instruction Interface Enable Bit
   DN : BOOL; {visible}   // Instruction Interface Done Bit
   IP : BOOL; {visible}   // Instruction Interface InProcess Bit
   ER : BOOL; {visible}   // Instruction Interface Error Bit
END_VAR
VAR_IN_OUT
   map_SignInput : SINT[32]; {required}   // Ethernet/IP LEDSIGN.I Data I/O Mapping
   map_SignOutput : SINT[496]; {required}   // Ethernet/IP LEDSIGN.O Data I/O Mapping
   Packet1Sent : STRING; {required}   // The actual packet sent to the sign (Packet1)
   Packet2Sent : STRING; {required}   // The actual packet sent to the sign (Packet2)
   Packet3Sent : STRING; {required}   // The actual packet sent to the sign (Packet3)
   Packet4Sent : STRING; {required}   // The actual packet sent to the sign (Packet4)
   Packet5Sent : STRING; {required}   // The actual packet sent to the sign (Packet5)
   Packet6Sent : STRING; {required}   // The actual packet sent to the sign (Packet6)
END_VAR
VAR
   SEQ : DINT;   // Sequence Number
   OktoCycle : BOOL;   // Ok to Cycle
   InCycle : BOOL;   // Incycle
   Error : BOOL;   // Error
   Enabled : BOOL;   // Enable ON Bit
   Done : BOOL;   // Done
   Disabled : BOOL;   // Disabled OFF Bit
   SignETX : STRING := '^C';   // DO NOT EDIT = ^C
   SignTextMessage1 : STRING;
   SignColor : STRING;
   SignFont : STRING;
   SignFileLabel : STRING;
   SignCommandCode : STRING;
   SignSOH : STRING := '^A';   // DO NOT EDIT = ^A
   SignAddress : STRING;
   SignSTX : STRING := '^B';   // DO NOT EDIT = ^B
   Packet : STRING[7];   // Packet Array to send to sign
   SignFontCommand : STRING := '^F';   // DO NOT EDIT = ^F
   SignColorCommand : STRING := '^O';   // DO NOT EDIT = ^O
   SignAlignCommand : STRING := '^G';   // DO NOT EDIT = ^G
   SignAlign : STRING;
   SignSpeedCommand : STRING := '^I';   // DO NOT EDIT = ^I
   SignSpeed : STRING;
   SignEffectCommand : STRING := '^E';   // DO NOT EDIT = ^E
   SignEffect : STRING;
   SignPauseCommand : STRING := '^J';   // DO NOT EDIT = ^J
   SignPause : STRING;
   SignTextMessage4 : STRING;
   SignTextMessage3 : STRING;
   SignTextMessage2 : STRING;
   SignNextLine : STRING := '^M';   // DO NOT EDIT = ^M
   SignNULL : STRING;
   SignVariableFont : STRING;
   SignVariableColor : STRING;
   SignVariable4 : STRING;
   SignVariable3 : STRING;
   SignVariable2 : STRING;
   SignVariable1 : STRING;
   SignVariableCommand : STRING := '^N';   // DO NOT EDIT = ^N
   Select : DINT;   // Packet Array Select
   TotalPacketCount : DINT[7];   // Total Character Count
   PacketMax : DINT := 82;   // Max Packet Count
   PacketCount : DINT[7];
   Packet6Offset : DINT;
   Packet5Offset : DINT;
   Packet4Offset : DINT;
   Packet3Offset : DINT;
   Packet2Offset : DINT;
   Packet1Offset : DINT;
   SignMode2Command : STRING := 'H';   // DO NOT EDIT = H (make it hold)
   SignAttributeCommand : STRING := '^H';   // DO NOT EDIT = ^H
   SignAttribute : STRING;
   SignVariableAttribute : STRING;
END_VAR

ROUTINE EnableInFalse   (* ladder *)
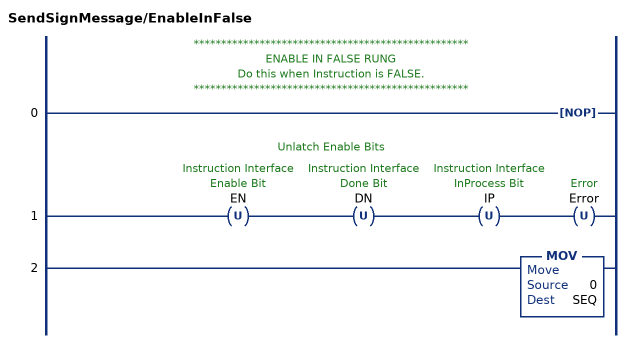
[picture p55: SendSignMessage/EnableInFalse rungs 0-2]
   // **************************************************
   // ENABLE IN FALSE RUNG
   // Do this when Instruction is FALSE.
   // **************************************************
   0: NOP();
   // Unlatch Enable Bits
   1: OTU(EN)OTU(DN)OTU(IP)OTU(Error);
   2: MOV(0,SEQ);
END_ROUTINE
